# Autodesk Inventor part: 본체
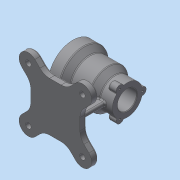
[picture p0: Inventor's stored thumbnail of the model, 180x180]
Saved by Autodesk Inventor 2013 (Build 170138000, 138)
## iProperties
Created: 2017-03
Part Number: 본체
Material: 일반
Document SubType Name: Modeling
Designer: Administrator
Density: 1 g/cm^3
Author: Administrator
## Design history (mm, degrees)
sketch "스케치1"
  geometry: L1 (-50, 0)-(50, 0); L2 (-50, 45)-(-30, 45); L3 (-30, 45)-(-19, 36); L4 (-19, 36)-(15, 36); L5 (15, 36)-(27, 27.5); L6 (27, 27.5)-(50, 27.5); L7 (50, 27.5)-(50, 17.5); L8 (50, 17.5)-(23, 17.5); L9 (20, 20.5)-(20, 23); L10 (17, 26)-(-24, 26); L11 (-27, 29)-(-27, 32); L12 (-30, 35)-(-50, 35); L13 (-50, 35)-(-50, 45); A1 r 3 centre (-30, 32) between (-27, 32) and (-30, 35); A2 r 3 centre (17, 23) between (20, 23) and (17, 26); A3 r 3 centre (23, 20.5) between (20, 20.5) and (23, 17.5); A4 r 3 centre (-24, 29) between (-27, 29) and (-24, 26); 5 further points
  constraints: 26 end point, 9 parallel, 8 point on circle, 8 tangent, 6 point on line, 4 centre point, 3 equal radius, 2 vertical alignment, 1 coincident, 1 horizontal, 1 midpoint, 1 perpendicular
  dimensions: "d0" = 100 distance of L1.start L1.end; "d14" = 70 diameter of L12 L1; "d15" = 52 diameter of L10 L1; "d16" = 35 diameter of L8 L1; "d17" = 23 distance of point (-27, 35) L12.end; "d18" = 47 distance of point (20, 26) point (-27, 26); "d19" = 20 distance of L2.start L2.end; "d20" = 31 distance from line of L3.end L13; "d21" = 65 distance from line of L4.end L13; "d22" = 23 distance of L5.end L6.end; "d23" = 90 diameter of L2 L1; "d24" = 72 diameter of L4 L1; "d25" = 55 diameter of L6 L1; "d26" = 3 radius of A1
revolve "회전1" sketch "스케치1" stored, may be unused: angle "d27" = 90 deg
sketch "스케치2"
  geometry: C1 r 17.5 at (0, 0) reference; C2 r 7 at (0, 27.5); 1 further point
  constraints: 2 vertical alignment, 1 centre point, 1 other
  dimensions: "d28" = 14 diameter of C2
extrude "돌출1" join sketch "스케치2" distance "d30" = 15; taper "d31" = 0 deg
fillet "모깎기1" dims "d32" = 3
fillet "모깎기2" dims "d33" = 1
sketch "스케치3"
  geometry: A1 r 7 centre (0, 0) between (6.999, -0.127) and (-6.999, -0.127) reference; 1 further point
  constraints: 1 coincident
hole "구멍1" sketch "스케치3" at (0, 0) diameter "d34" = 3.242; stored, may be unused: countersink angle "d38" = 90 deg, drill point angle "d40" = 118 deg; dims "d35" = 9, "d36" = 4, "d37" = 2, "d39" = 11
sketch "스케치4" dims "d44" = 80
  geometry: C1 r 45 at (0, 0) reference; 1 further point
  constraints: 2 vertical alignment, 2 other
hole "구멍2" sketch "스케치4" at (0, 40) diameter "d46" = 3.242; stored, may be unused: countersink angle "d50" = 90 deg, drill point angle "d52" = 118 deg; dims "d47" = 9, "d48" = 4, "d49" = 2, "d51" = 11
node "작업 평면1"
sketch "스케치5"
  geometry: L1 (45, 45)-(-45, 45); L2 (-45, 45)-(-45, -45); L3 (-45, -45)-(45, -45); L4 (45, -45)-(45, 45); L5 (45, 45)-(-45, -45); L6 (-45, 45)-(45, -45); L7 (37.477, 61.518)-(28.281, 52.322); L8 (61.518, 37.477)-(52.322, 28.281); L9 (61.518, -37.477)-(52.322, -28.281); L10 (37.477, -61.518)-(28.281, -52.322); L11 (-37.477, -61.518)-(-28.281, -52.322); L12 (-61.518, -37.477)-(-52.322, -28.281); L13 (-37.477, 61.518)-(-28.281, 52.322); L14 (-61.518, 37.477)-(-52.322, 28.281); A1 r 70 centre (0, 0) between (49.497, 49.497) and (49.497, -49.497); A2 r 17 centre (49.497, 49.497) between (37.477, 61.518) and (61.518, 37.477); A3 r 17 centre (49.497, -49.497) between (61.518, -37.477) and (37.477, -61.518); A4 r 17 centre (-49.497, -49.497) between (-37.477, -61.518) and (-61.518, -37.477); A5 r 17 centre (-49.497, 49.497) between (-37.477, 61.518) and (-61.518, 37.477); A6 r 25 centre (10.603, 70) between (10.603, 45) and (28.281, 52.322); A7 r 25 centre (70, 10.603) between (52.322, 28.281) and (45, 10.603); A8 r 25 centre (70, -10.603) between (45, -10.603) and (52.322, -28.281); A9 r 25 centre (10.603, -70) between (28.281, -52.322) and (10.603, -45); A10 r 25 centre (-70, -10.603) between (-52.322, -28.281) and (-45, -10.603); A11 r 25 centre (-10.603, 70) between (-28.281, 52.322) and (-10.603, 45); A12 r 25 centre (-70, 10.603) between (-45, 10.603) and (-52.322, 28.281); A13 r 25 centre (-10.603, -70) between (-10.603, -45) and (-28.281, -52.322); 1 further point
  constraints: 28 end point, 28 point on circle, 24 tangent, 13 centre point, 10 equal radius, 8 point on line, 6 parallel, 6 perpendicular, 2 horizontal alignment, 2 midpoint, 2 vertical alignment, 1 coincident, 1 horizontal
  dimensions: "d57" = 140 diameter of A1; "d59" = 90 deg dimension on point (0, 0) A5.centre A1.start; "d61" = 34 diameter of A2; "d62" = 90 distance of L3.end L1.start; "d63" = 25 radius of A6
extrude "돌출2" join sketch "스케치5" distance "d64" = 12; taper "d65" = 0 deg
sketch "스케치6"
  geometry: C1 r 5 at (-49.497, 49.497); C2 r 5 at (-49.497, -49.497); C3 r 5 at (49.497, -49.497); C4 r 5 at (49.497, 49.497); A1 r 17 centre (49.497, 49.497) between (61.518, 37.477) and (37.477, 61.518) reference; A2 r 17 centre (-49.497, 49.497) between (-37.477, 61.518) and (-61.518, 37.477) reference; A3 r 17 centre (-49.497, -49.497) between (-61.518, -37.477) and (-37.477, -61.518) reference; A4 r 17 centre (49.497, -49.497) between (37.477, -61.518) and (61.518, -37.477) reference; 1 further point
  constraints: 4 centre point, 4 coincident, 3 equal radius
  dimensions: "d66" = 10 diameter of C1
extrude "돌출3" cut sketch "스케치6" stored distance "d68" = 12; taper "d69" = 0 deg
fillet "모깎기3" dims "d70" = 3
sketch "스케치7"
  geometry: L1 (-70, 39.598)-(-70, 30.402) reference; L2 (-70, 10.603)-(-70, 30.402) reference; L3 (-31.096, 18.14)-(-70, 25); 2 further points
  constraints: 2 end point, 1 point on line, 2 other
  dimensions: "d71" = 100 deg angle of L3 L1; "d72" = 25 vertical distance of L3.end point (0, 0)
feature "리브1" sketch "스케치7" dims "d73" = 25, "d74" = 8, "d75" = 0, "d76" = 0, "d77" = 1, "d78" = 1
sketch "스케치8"
  geometry: L1 (-50, -45)-(-30, -45) reference; L2 (-30, -45)-(-19, -36) reference; L3 (-39.598, -70)-(-30.402, -70) reference; L4 (-10.603, -70)-(-30.402, -70) reference; L5 (-37, -45)-(-37, -70); 1 further point
  constraints: 2 end point, 2 point on line, 1 vertical
  dimensions: "d79" = 37 distance from line of L5 point (0, 0)
feature "리브2" sketch "스케치8" dims "d80" = 25, "d81" = 8, "d82" = 0, "d83" = 0, "d84" = 1, "d85" = 1
sketch "스케치9"
  geometry: L1 (4, -36)-(15, -36) reference; L2 (15, -36)-(27, -27.5) reference; L3 (30.402, -70)-(10.603, -70) reference; L4 (30.402, -70)-(39.598, -70) reference; L5 (27, -27.5)-(50, -27.5) reference; L6 (37, -27.5)-(37, -70); 1 further point
  constraints: 2 end point, 2 point on line, 1 vertical
  dimensions: "d86" = 37 distance from line of L6 point (0, 0)
feature "리브3" sketch "스케치9" dims "d87" = 25, "d88" = 8, "d89" = 0, "d90" = 0, "d91" = 1, "d92" = 1
chamfer "모따기1" distance "d93" = 1; stored, may be unused: second distance "d94" = 2, angle "d95" = 45 deg
fillet "모깎기4" dims "d96" = 3
fillet "모깎기5" dims "d97" = 3
node "작업 평면2"
sketch "스케치10"
  geometry: L1 (50, 45)-(50, -45) reference; C1 r 5 at (0, 0); 1 further point
  constraints: 1 centre point, 1 coincident
  dimensions: "d99" = 50 distance from line of C1.centre L1; "d100" = 10 diameter of C1
extrude "돌출4" join sketch "스케치10" stored distance "d101" = 12; taper "d102" = 0 deg
fillet "모깎기6" dims "d103" = 3
sketch "스케치11"
  geometry: C1 r 5 at (0, 0) reference; 1 further point
  constraints: 1 coincident
hole "구멍3" sketch "스케치11" at (0, 0) diameter "d104" = 4.134; stored, may be unused: countersink angle "d108" = 90 deg, drill point angle "d110" = 118 deg; dims "d105" = 9, "d106" = 4, "d107" = 2, "d109" = 11
sketch "스케치12"
  geometry: L1 (45, -10.603)-(45, 10.603) reference; 2 further points
  constraints: 1 other
  dimensions: "d111" = 35 distance of point (0, -35) point (0, 0); "d112" = 45 distance from line of point (0, -35) L1
feature "엠보싱1" sketch "스케치12" dims "d0" = 100, "d14" = 70, "d15" = 52, "d16" = 35, "d17" = 23, "d18" = 47, "d19" = 20, "d20" = 31, "d21" = 65, "d22" = 23, "d23" = 90, "d24" = 72, "d25" = 55, "d26" = 3, "d113" = 0.5, "d114" = 0
node "솔리드1"
pattern_circular "원형 패턴1" dims "d42" = 360 deg
pattern_circular "원형 패턴2" dims angle "d54" = 360 deg
mirror "대칭1"
other parameters: "d56" = -82
